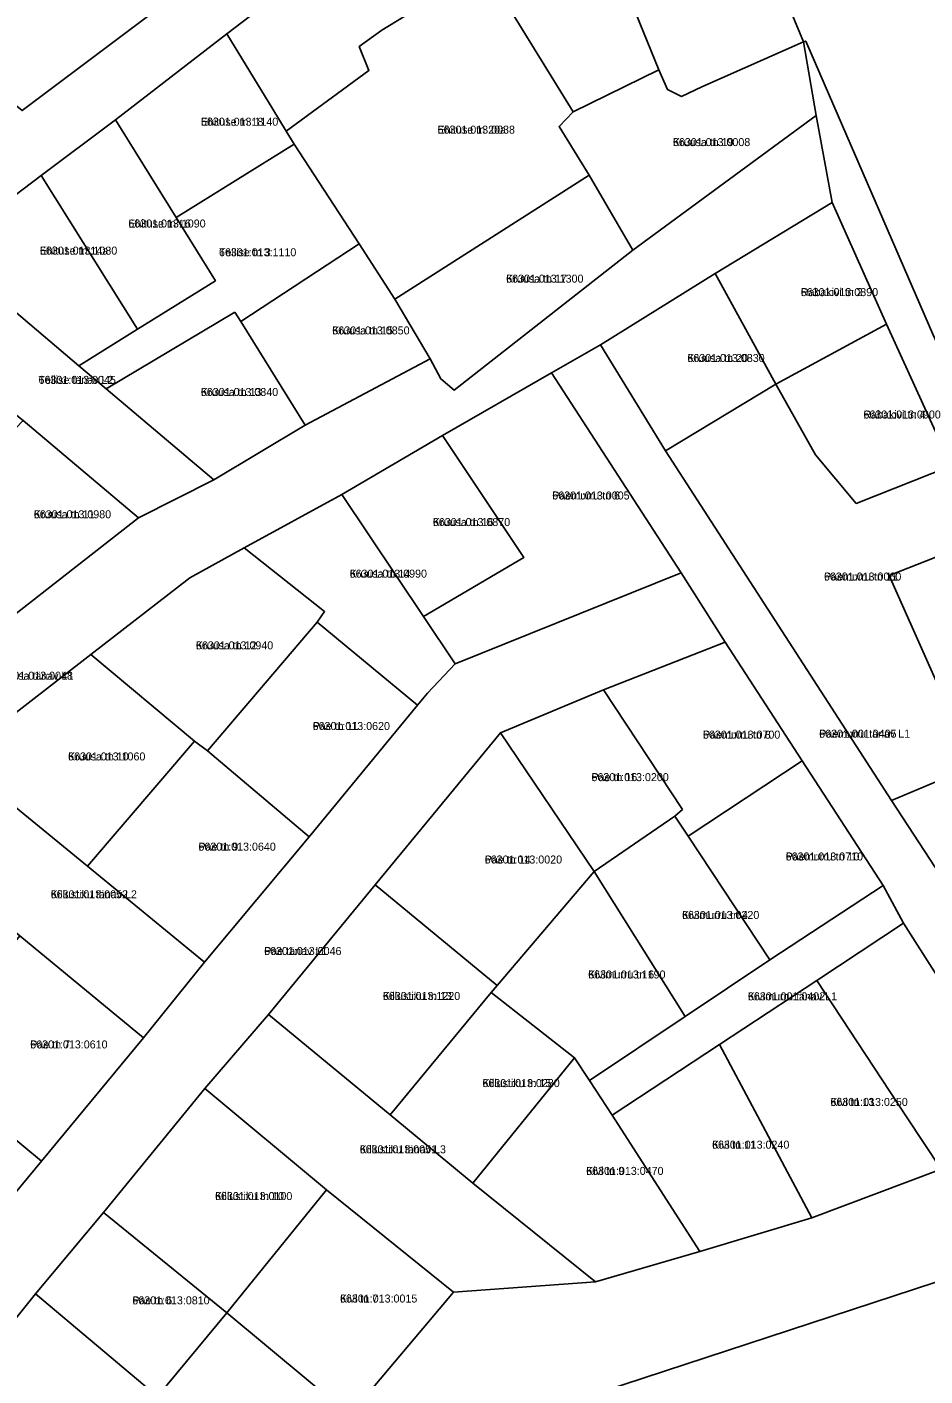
# Model space of a CAD drawing. Extents: x 632278 to 636344, y 6578401 to 6583362.
# Drawn here: x 635633.8 to 635802.2, y 6580365.1 to 6580618 of the extents above; entities that cross this region are included whole.
import ezdxf

# ---------------------------------------------------------------- set-up
doc = ezdxf.new("R2010")
doc.units = 0
for name, color, linetype in [('L_AADRESS', 7, 'Continuous'), ('PIIR', 7, 'Continuous'), ('TUNNUS', 7, 'Continuous')]:
    doc.layers.add(name, color=color, linetype=linetype)

msp = doc.modelspace()

# ---------------------------------------------------------------- linework, layer by layer
at = {"layer": 'PIIR'}
for points in [[(635709.32, 6580645.71), (635731.44, 6580661.66), (635742.15, 6580634.86), (635752.28, 6580609.94), (635736.22, 6580602.06), (635719.41, 6580629.34)], [(635709.32, 6580645.71), (635719.41, 6580629.34), (635736.22, 6580602.06), (635733.57, 6580599.31), (635739.18, 6580590.21), (635702.79, 6580566.93), (635696.06, 6580577.34), (635683.87, 6580595.98), (635682.39, 6580598.42), (635697.9, 6580609.77), (635696.11, 6580614.28), (635700.32, 6580617.35), (635709.13, 6580622.74), (635714.98, 6580626.76), (635705.3, 6580642.63)], [(635705.3, 6580642.63), (635714.98, 6580626.76), (635709.13, 6580622.74), (635700.32, 6580617.35), (635696.11, 6580614.28), (635697.9, 6580609.77), (635682.39, 6580598.42), (635679.87, 6580602.57), (635671.26, 6580616.66)], [(635767.07, 6580644.87), (635779.38, 6580615.15), (635760.32, 6580606.71), (635756.52, 6580604.92), (635753.89, 6580606.23), (635752.28, 6580609.94), (635742.15, 6580634.86), (635762.21, 6580642.8)], [(635633.91, 6580639.12), (635657.14, 6580620.49), (635632.93, 6580602.28), (635609.73, 6580621.07)], [(635650.38, 6580600.58), (635671.26, 6580616.66), (635679.87, 6580602.57), (635682.39, 6580598.42), (635683.87, 6580595.98), (635661.77, 6580582.24)], [(635752.28, 6580609.94), (635753.89, 6580606.23), (635756.52, 6580604.92), (635760.32, 6580606.71), (635779.38, 6580615.15), (635781.75, 6580601.34), (635747.38, 6580576.12), (635739.18, 6580590.21), (635733.57, 6580599.31), (635736.22, 6580602.06)], [(635781.75, 6580601.34), (635779.38, 6580615.15), (635779.82, 6580615.31), (635785.06, 6580603.2), (635803.65, 6580560.36), (635900.69, 6580352.93), (635895.15, 6580351.15), (635897.37, 6580356.64), (635886.34, 6580374.71), (635877.84, 6580372.09), (635876.62, 6580376.41), (635876, 6580378.35), (635882.84, 6580380.46), (635867.04, 6580406.32), (635856.08, 6580424.25), (635845.19, 6580449.09), (635837.37, 6580467.32), (635828.8, 6580486.5), (635812.96, 6580522.01), (635807.08, 6580535.72), (635794.95, 6580562.28), (635784.79, 6580585.04)], [(635650.38, 6580600.58), (635661.77, 6580582.24), (635669.13, 6580570.4), (635654.53, 6580561.31), (635636.48, 6580590.11)], [(635672.79, 6580564.51), (635648.64, 6580550.15), (635643.54, 6580554.47), (635654.53, 6580561.31), (635669.13, 6580570.4), (635661.77, 6580582.24), (635683.87, 6580595.98), (635696.06, 6580577.34), (635673.87, 6580562.78)], [(635617.94, 6580576.14), (635636.48, 6580590.11), (635654.53, 6580561.31), (635643.54, 6580554.47)], [(635711.4, 6580551.98), (635709.42, 6580555.74), (635702.79, 6580566.93), (635739.18, 6580590.21), (635747.38, 6580576.12), (635713.89, 6580549.88)], [(635762.81, 6580571.78), (635784.79, 6580585.04), (635794.95, 6580562.28), (635774.19, 6580550.99)], [(635673.87, 6580562.78), (635696.06, 6580577.34), (635702.79, 6580566.93), (635709.42, 6580555.74), (635685.95, 6580543.33)], [(635617.94, 6580576.14), (635643.54, 6580554.47), (635648.64, 6580550.15), (635668.82, 6580533.07), (635654.74, 6580525.98), (635633.09, 6580544.17), (635615.32, 6580558.21), (635598.91, 6580571.74)], [(635741.33, 6580558.41), (635762.81, 6580571.78), (635774.19, 6580550.99), (635753.51, 6580538.54)], [(635672.79, 6580564.51), (635673.87, 6580562.78), (635685.95, 6580543.33), (635668.82, 6580533.07), (635648.64, 6580550.15)], [(635781.66, 6580537.75), (635774.19, 6580550.99), (635794.95, 6580562.28), (635807.08, 6580535.72), (635789.28, 6580528.67)], [(635741.33, 6580558.41), (635753.51, 6580538.54), (635795.88, 6580472.95), (635807.2, 6580455.67), (635820.1, 6580435.44), (635832.52, 6580414.38), (635823.15, 6580410.76), (635798.17, 6580449.98), (635794.33, 6580457.05), (635779.16, 6580480.43), (635764.72, 6580502.67), (635756.47, 6580515.62), (635732.14, 6580553.12)], [(635708.12, 6580507.46), (635726.95, 6580518.49), (635711.68, 6580541.37), (635732.14, 6580553.12), (635756.47, 6580515.62), (635714.06, 6580498.56)], [(635774.19, 6580550.99), (635781.66, 6580537.75), (635789.28, 6580528.67), (635807.08, 6580535.72), (635812.96, 6580522.01), (635795.43, 6580515.14), (635811.35, 6580479.44), (635795.88, 6580472.95), (635753.51, 6580538.54)], [(635620.87, 6580516.71), (635613.1, 6580523.3), (635633.09, 6580544.17), (635654.74, 6580525.98), (635631.21, 6580507.57)], [(635711.68, 6580541.37), (635726.95, 6580518.49), (635708.12, 6580507.46), (635692.85, 6580530.33)], [(635689.59, 6580508.37), (635674.55, 6580520.3), (635692.85, 6580530.33), (635708.12, 6580507.46), (635714.06, 6580498.56), (635708.89, 6580493.06), (635707.04, 6580490.82), (635688.21, 6580506.37)], [(635795.43, 6580515.14), (635812.96, 6580522.01), (635828.8, 6580486.5), (635811.35, 6580479.44)], [(635665.2, 6580484.07), (635645.77, 6580500.31), (635664.35, 6580514.69), (635674.55, 6580520.3), (635689.59, 6580508.37), (635688.21, 6580506.37), (635667.68, 6580482.3)], [(635591.82, 6580351.91), (635608.04, 6580371.06), (635623.68, 6580389.87), (635636.52, 6580405.39), (635655.62, 6580428.51), (635667.08, 6580442.68), (635686.71, 6580466.19), (635707.04, 6580490.82), (635708.89, 6580493.06), (635714.06, 6580498.56), (635756.47, 6580515.62), (635764.72, 6580502.67), (635741.92, 6580493.69), (635722.58, 6580485.64), (635699.1, 6580457.17), (635679.06, 6580432.87), (635667.18, 6580418.97), (635648.14, 6580395.77), (635635.42, 6580380.52), (635622.77, 6580364.81), (635603.53, 6580341.98)], [(635688.21, 6580506.37), (635707.04, 6580490.82), (635686.71, 6580466.19), (635667.68, 6580482.3)], [(635755.27, 6580470.05), (635756.69, 6580471.29), (635741.92, 6580493.69), (635764.72, 6580502.67), (635779.16, 6580480.43), (635757.78, 6580466.3)], [(635645.77, 6580500.31), (635665.2, 6580484.07), (635645.18, 6580460.65), (635620.52, 6580480.76)], [(635741.92, 6580493.69), (635756.69, 6580471.29), (635755.27, 6580470.05), (635740.16, 6580459.69), (635722.58, 6580485.64)], [(635795.88, 6580472.95), (635811.35, 6580479.44), (635828.8, 6580486.5), (635837.37, 6580467.32), (635807.2, 6580455.67)], [(635645.18, 6580460.65), (635665.2, 6580484.07), (635667.68, 6580482.3), (635686.71, 6580466.19), (635667.08, 6580442.68)], [(635722.58, 6580485.64), (635740.16, 6580459.69), (635721.99, 6580438.31), (635699.1, 6580457.17)], [(635609.37, 6580466.7), (635620.52, 6580480.76), (635645.18, 6580460.65), (635667.08, 6580442.68), (635655.62, 6580428.51), (635632.49, 6580447.6)], [(635757.78, 6580466.3), (635779.16, 6580480.43), (635794.33, 6580457.05), (635773.06, 6580443.11)], [(635755.27, 6580470.05), (635757.78, 6580466.3), (635773.06, 6580443.11), (635757.22, 6580432.51), (635740.16, 6580459.69)], [(635720.82, 6580436.96), (635721.99, 6580438.31), (635740.16, 6580459.69), (635757.22, 6580432.51), (635739.27, 6580420.49), (635736.49, 6580424.74)], [(635679.06, 6580432.87), (635699.1, 6580457.17), (635721.99, 6580438.31), (635720.82, 6580436.96), (635701.89, 6580414.04)], [(635739.27, 6580420.49), (635757.22, 6580432.51), (635773.06, 6580443.11), (635794.33, 6580457.05), (635798.17, 6580449.98), (635781.91, 6580439.24), (635763.67, 6580427.25), (635743.52, 6580413.97)], [(635798.73, 6580413.67), (635781.91, 6580439.24), (635798.17, 6580449.98), (635823.15, 6580410.76), (635808.49, 6580405.2), (635805.21, 6580403.87)], [(635613.29, 6580424.6), (635632.49, 6580447.6), (635655.62, 6580428.51), (635636.52, 6580405.39)], [(635763.67, 6580427.25), (635781.91, 6580439.24), (635798.73, 6580413.67), (635805.21, 6580403.87), (635780.95, 6580394.74)], [(635701.89, 6580414.04), (635720.82, 6580436.96), (635736.49, 6580424.74), (635717.37, 6580401.27)], [(635667.18, 6580418.97), (635679.06, 6580432.87), (635701.89, 6580414.04), (635717.37, 6580401.27), (635740.39, 6580382.76), (635713.75, 6580380.81), (635689.95, 6580399.99)], [(635759.94, 6580388.42), (635743.52, 6580413.97), (635763.67, 6580427.25), (635780.95, 6580394.74)], [(635623.68, 6580389.87), (635600.45, 6580409.07), (635613.29, 6580424.6), (635636.52, 6580405.39)], [(635736.49, 6580424.74), (635739.27, 6580420.49), (635743.52, 6580413.97), (635759.94, 6580388.42), (635740.39, 6580382.76), (635717.37, 6580401.27)], [(635671.28, 6580376.92), (635648.14, 6580395.77), (635667.18, 6580418.97), (635689.95, 6580399.99)], [(635694.32, 6580357.75), (635671.28, 6580376.92), (635689.95, 6580399.99), (635713.75, 6580380.81)], [(635648.14, 6580395.77), (635671.28, 6580376.92), (635658.3, 6580361.28), (635635.42, 6580380.52)], [(635737.74, 6580360.91), (635808.04, 6580383.95), (635813.96, 6580358.43), (635815.34, 6580352.49), (635767.28, 6580336.34)], [(635622.77, 6580364.81), (635635.42, 6580380.52), (635658.3, 6580361.28), (635645.54, 6580346.14), (635638.12, 6580352.4)], [(635671.28, 6580376.92), (635694.32, 6580357.75), (635681.51, 6580342.36), (635658.3, 6580361.28)]]:
    msp.add_lwpolyline(points, close=True, dxfattribs=at)
for points in [[(635705.3, 6580642.63), (635671.26, 6580616.66), (635650.38, 6580600.58), (635636.48, 6580590.11), (635617.94, 6580576.14)], [(635632.93, 6580602.28), (635657.14, 6580620.49)], [(635631.21, 6580507.57), (635654.74, 6580525.98), (635668.82, 6580533.07), (635685.95, 6580543.33), (635709.42, 6580555.74), (635711.4, 6580551.98), (635713.89, 6580549.88), (635747.38, 6580576.12), (635781.75, 6580601.34), (635784.79, 6580585.04), (635762.81, 6580571.78), (635741.33, 6580558.41), (635732.14, 6580553.12), (635711.68, 6580541.37), (635692.85, 6580530.33), (635674.55, 6580520.3), (635664.35, 6580514.69), (635645.77, 6580500.31), (635620.52, 6580480.76)], [(635808.04, 6580383.95), (635737.74, 6580360.91), (635732.67, 6580358.81), (635708.51, 6580350.92), (635705.9, 6580347.87), (635693.33, 6580332.57), (635680.62, 6580317.33), (635694.14, 6580305.99), (635675.14, 6580283.28), (635649.69, 6580303.82), (635668.71, 6580327.17), (635681.51, 6580342.36), (635694.32, 6580357.75), (635713.75, 6580380.81), (635740.39, 6580382.76), (635759.94, 6580388.42), (635780.95, 6580394.74), (635805.21, 6580403.87)]]:
    msp.add_lwpolyline(points, dxfattribs=at)

# ---------------------------------------------------------------- texts
at = {"layer": 'L_AADRESS'}
for s, p in [('Ehituse tn 18', (635666.42, 6580599.45)), ('Ehituse tn 20a', (635710.79, 6580597.96)), ('Kruusa tn 19', (635754.91, 6580595.63)), ('Ehituse tn 16', (635652.8, 6580580.37)), ('Ehituse tn 14a', (635636.23, 6580575.29)), ('Tellise tn 3', (635669.8, 6580574.98)), ('Kruusa tn 17', (635723.64, 6580570.04)), ('Rabakivi tn 2', (635778.88, 6580567.51)), ('Kruusa tn 15', (635691.04, 6580560.33)), ('Kruusa tn 20', (635757.61, 6580555.16)), ('Tellise tänav L2', (635635.97, 6580551.06)), ('Kruusa tn 13', (635666.4, 6580548.79)), ('Rabakivi tn 4', (635790.63, 6580544.57)), ('Paemurru tn 6', (635732.29, 6580529.39)), ('Kruusa tn 11', (635635.08, 6580525.87)), ('Kruusa tn 16', (635709.9, 6580524.41)), ('Kruusa tn 14', (635694.3, 6580514.74)), ('Paemurru tn 11', (635783.23, 6580514.2)), ('Kruusa tn 12', (635665.47, 6580501.3)), ('Kruusa tänav L1', (635627.91, 6580495.61)), ('Pae tn 11', (635687.36, 6580486.18)), ('Paemurru tn 8', (635760.54, 6580484.57)), ('Paemurru tänav L1', (635782.33, 6580484.74)), ('Kruusa tn 10', (635641.5, 6580480.48)), ('Pae tn 16', (635739.63, 6580476.6)), ('Pae tn 9', (635665.95, 6580463.57)), ('Paemurru tn 10', (635776.05, 6580461.73)), ('Pae tn 14', (635719.63, 6580461.16)), ('Killustiku tänav L2', (635638.24, 6580454.64)), ('Kivimurru tn 4', (635756.61, 6580450.76)), ('Pae tänav L1', (635678.27, 6580444.01)), ('Kivimurru tn 6', (635739.02, 6580439.61)), ('Killustiku tn 13', (635700.53, 6580435.58)), ('Kivimurru tänav L1', (635768.97, 6580435.51)), ('Pae tn 7', (635634.41, 6580426.5)), ('Killustiku tn 15', (635719.19, 6580419.25)), ('Kivi tn 13', (635784.44, 6580415.72)), ('Killustiku tänav L3', (635696.18, 6580406.84)), ('Kivi tn 11', (635762.24, 6580407.71)), ('Kivi tn 9', (635738.65, 6580402.79)), ('Killustiku tn 10', (635669.05, 6580398.08)), ('Pae tn 6', (635653.55, 6580378.53)), ('Kivi tn 7', (635692.49, 6580378.87))]:
    msp.add_text(s, height=1.5, dxfattribs=at).set_placement(p)
at = {"layer": 'TUNNUS'}
for s, p in [('66301:013:1140', (635666.42, 6580599.45)), ('66301:013:0038', (635710.79, 6580597.96)), ('66301:013:0008', (635754.91, 6580595.63)), ('66301:013:1090', (635652.8, 6580580.37)), ('66301:013:1080', (635636.23, 6580575.29)), ('66301:013:1110', (635669.8, 6580574.98)), ('66301:013:1300', (635723.64, 6580570.04)), ('66301:013:0890', (635778.88, 6580567.51)), ('66301:013:0850', (635691.04, 6580560.33)), ('66301:013:0830', (635757.61, 6580555.16)), ('66301:013:0045', (635635.97, 6580551.06)), ('66301:013:0840', (635666.4, 6580548.79)), ('66301:013:0900', (635790.63, 6580544.57)), ('66301:013:0005', (635732.29, 6580529.39)), ('66301:013:0980', (635635.08, 6580525.87)), ('66301:013:0870', (635709.9, 6580524.41)), ('66301:013:0990', (635694.3, 6580514.74)), ('66301:013:0060', (635783.23, 6580514.2)), ('66301:013:0940', (635665.47, 6580501.3)), ('66301:013:0048', (635627.91, 6580495.61)), ('66301:013:0620', (635687.36, 6580486.18)), ('66301:013:0700', (635760.54, 6580484.57)), ('66301:001:0405', (635782.33, 6580484.74)), ('66301:013:1060', (635641.5, 6580480.48)), ('66301:013:0200', (635739.63, 6580476.6)), ('66301:013:0640', (635665.95, 6580463.57)), ('66301:013:0710', (635776.05, 6580461.73)), ('66301:013:0020', (635719.63, 6580461.16)), ('66301:013:0052', (635638.24, 6580454.64)), ('66301:013:0220', (635756.61, 6580450.76)), ('66301:013:0046', (635678.27, 6580444.01)), ('66301:013:1190', (635739.02, 6580439.61)), ('66301:013:1220', (635700.53, 6580435.58)), ('66301:001:0402', (635768.97, 6580435.51)), ('66301:013:0610', (635634.41, 6580426.5)), ('66301:013:0280', (635719.19, 6580419.25)), ('66301:013:0250', (635784.44, 6580415.72)), ('66301:013:0051', (635696.18, 6580406.84)), ('66301:013:0240', (635762.24, 6580407.71)), ('66301:013:0470', (635738.65, 6580402.79)), ('66301:013:0100', (635669.05, 6580398.08)), ('66301:013:0810', (635653.55, 6580378.53)), ('66301:013:0015', (635692.49, 6580378.87))]:
    msp.add_text(s, height=1.5, dxfattribs=at).set_placement(p)

doc.saveas('drawing.dxf')
